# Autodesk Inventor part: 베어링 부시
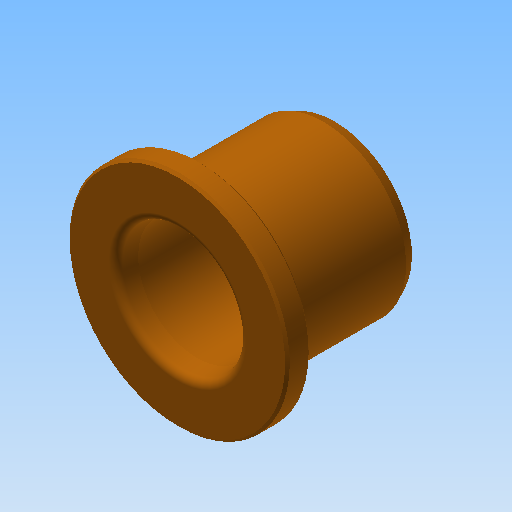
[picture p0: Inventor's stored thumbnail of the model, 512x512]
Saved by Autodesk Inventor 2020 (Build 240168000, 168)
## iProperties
Created: 2022-03
Part Number: 베어링 부시
Material: 황동, 연질
Document SubType Name: Modeling
Designer: mdu-01
Density: 1 g/cm^3
Appearance: 주황색
Author: mdu-01
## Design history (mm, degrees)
sketch "스케치1"
  geometry: L1 (0, 0)-(0, -20); L2 (7.941, 0)-(14, 0); L3 (14, 0)-(14, -3); L4 (14, -3)-(10.5, -3); L5 (10.5, -3)-(10.5, -18.6); L6 (9.844, -20)-(7.606, -20); L7 (7.5, -2.5)-(7.5, -19.4); L8 (7.5, -2.5)-(7.941, 0); L9 (7.5, -19.4)-(7.606, -20); L10 (10.5, -18.6)-(9.844, -20)
  constraints: 20 end point, 3 perpendicular, 2 horizontal alignment, 2 parallel, 1 horizontal, 1 vertical
  dimensions: "d0" = 21 diameter of L5 L1; "d2" = 28 diameter of L3 L1; "d3" = 20 distance of L1.start L1.end; "d4" = 3 distance of L2.end L3.end; "d5" = 15 diameter of L7 L1; "d6" = 10 deg angle of L7 L9; "d7" = 0.6 distance from line of L7.end L6; "d8" = 1.4 vertical distance of L5.end L6.start; "d9" = 25.0978 deg angle of L5 L10; "d10" = 10 deg angle of L7 L8; "d11" = 2.5 vertical distance of L7.start L2.start
revolve "회전1" sketch "스케치1" stored, may be unused: angle "d12" = 90 deg
chamfer "모따기1" distance "d13" = 0.3; stored, may be unused: second distance "d14" = 2, angle "d15" = 45 deg
fillet "모깎기1" dims "d16" = 0.3, "d17" = 1
node "솔리드1"
